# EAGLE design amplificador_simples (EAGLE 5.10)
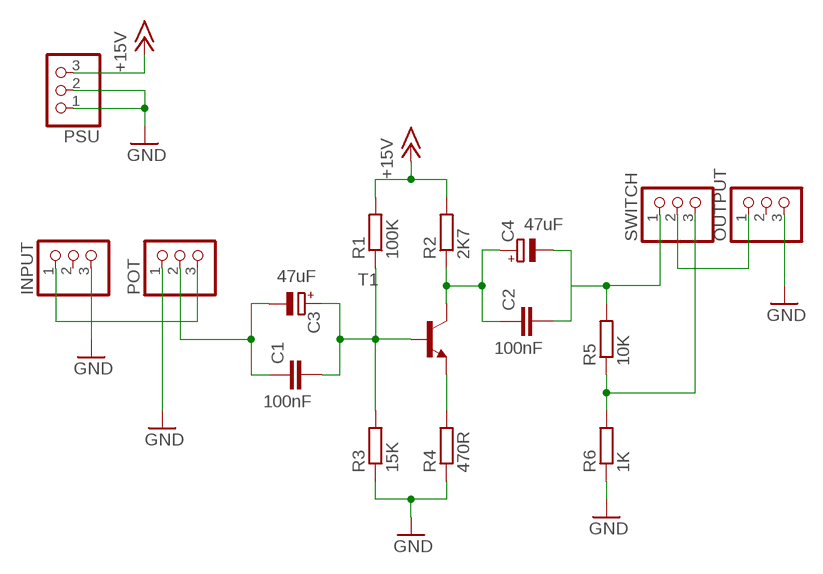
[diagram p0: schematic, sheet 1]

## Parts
C1  100nF  C-EU075-032X103  [C075-032X103]
C2  100nF  C-EU075-032X103  [C075-032X103]
C3  47uF  CPOL-EUE5-8.5  [E5-8,5]
C4  47uF  CPOL-EUE5-8.5  [E5-8,5]
INPUT  PINHD-1X3  [1X03]
OUTPUT  PINHD-1X3  [1X03]
POT  PINHD-1X3  [1X03]
PSU  PINHD-1X3  [1X03]
R1  100K  R-EU_0207/10  [0207/10]
R2  2K7  R-EU_0207/10  [0207/10]
R3  15K  R-EU_0207/10  [0207/10]
R4  470R  R-EU_0207/10  [0207/10]
R5  10K  R-EU_0207/10  [0207/10]
R6  1K  R-EU_0207/10  [0207/10]
SWITCH  PINHD-1X3  [1X03]
T1  BC548B-NPN-TO92-EBC  [TO92-EBC]

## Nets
+15V: PSU.3 R1.2 R2.2
GND: INPUT.3 OUTPUT.3 POT.1 PSU.1 PSU.2 R3.1 R4.1 R6.1
N$1: C2.1 C4.+ R2.1 T1.C
N$2: R4.2 T1.E
N$3: INPUT.1 POT.3
N$4: C1.2 C3.+ R1.1 R3.2 T1.B
N$5: R5.1 R6.2 SWITCH.3
N$6: OUTPUT.1 SWITCH.2
N$8: C2.2 C4.- R5.2 SWITCH.1
N$9: C1.1 C3.- POT.2
Unconnected: INPUT.2 OUTPUT.2

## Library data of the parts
C1 C2 = resistor:C-EU: CAPACITOR, European symbol
C3 C4 = resistor:CPOL-EU: POLARIZED CAPACITOR, European symbol
INPUT OUTPUT POT PSU SWITCH = pinhead:PINHD-1X3: PIN HEADER
R1-R6 = resistor:R-EU_: RESISTOR, European symbol
T1 = transistor:*-NPN-: NPN Transistror BF959 corrected 2008.03.06

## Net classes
0 default: width 0.635 mm, drill 0.635 mm, clearance 0.635 mm

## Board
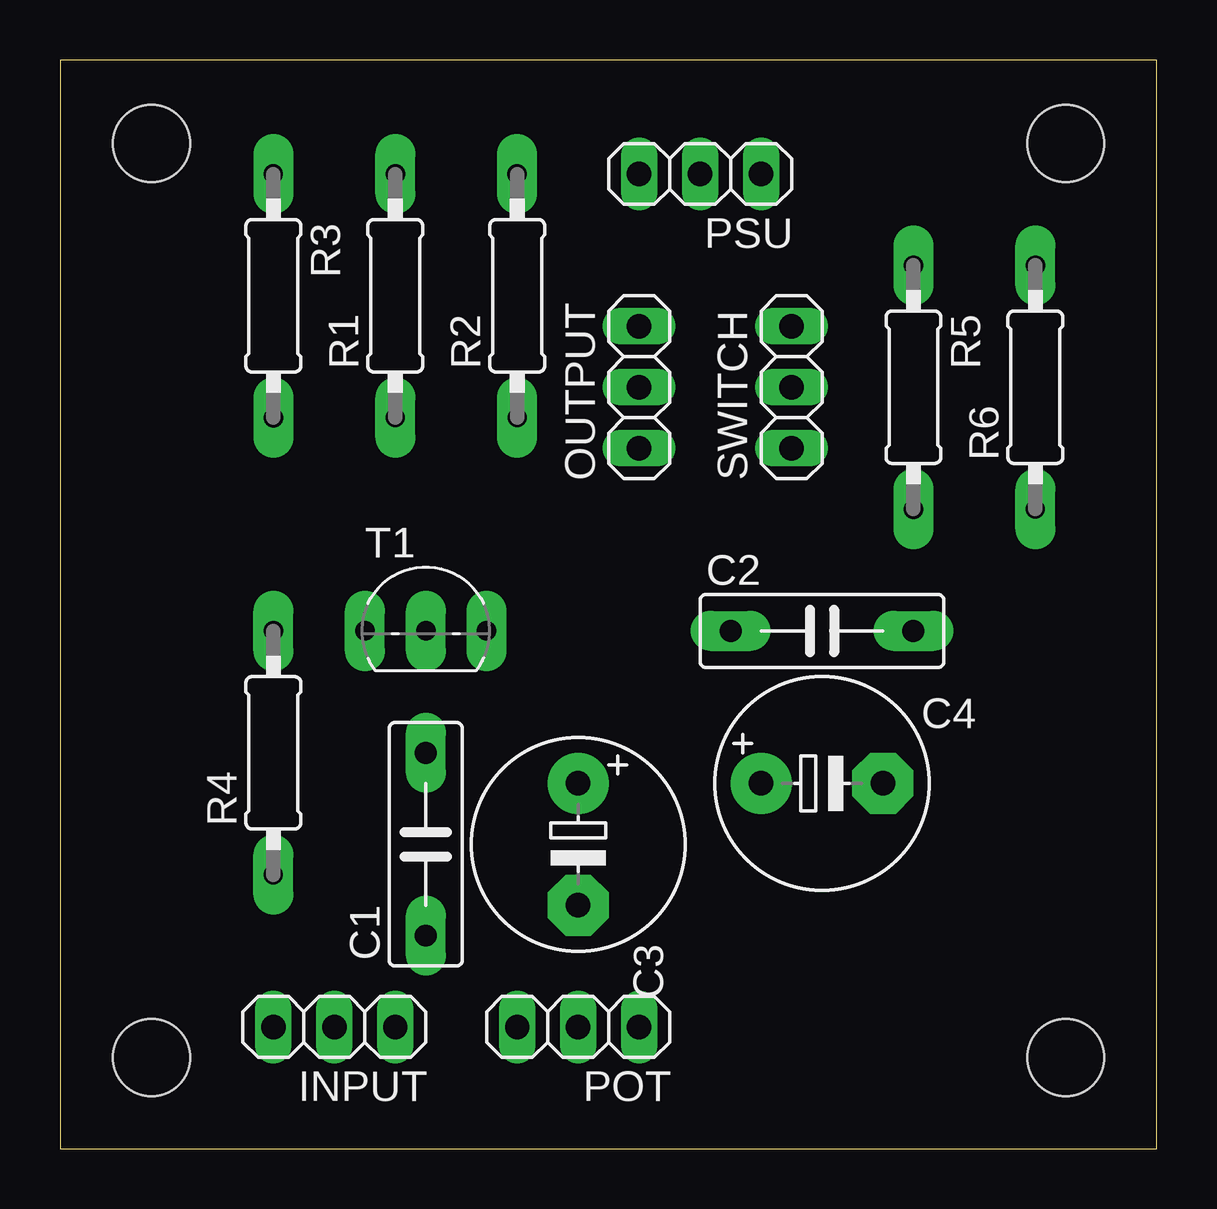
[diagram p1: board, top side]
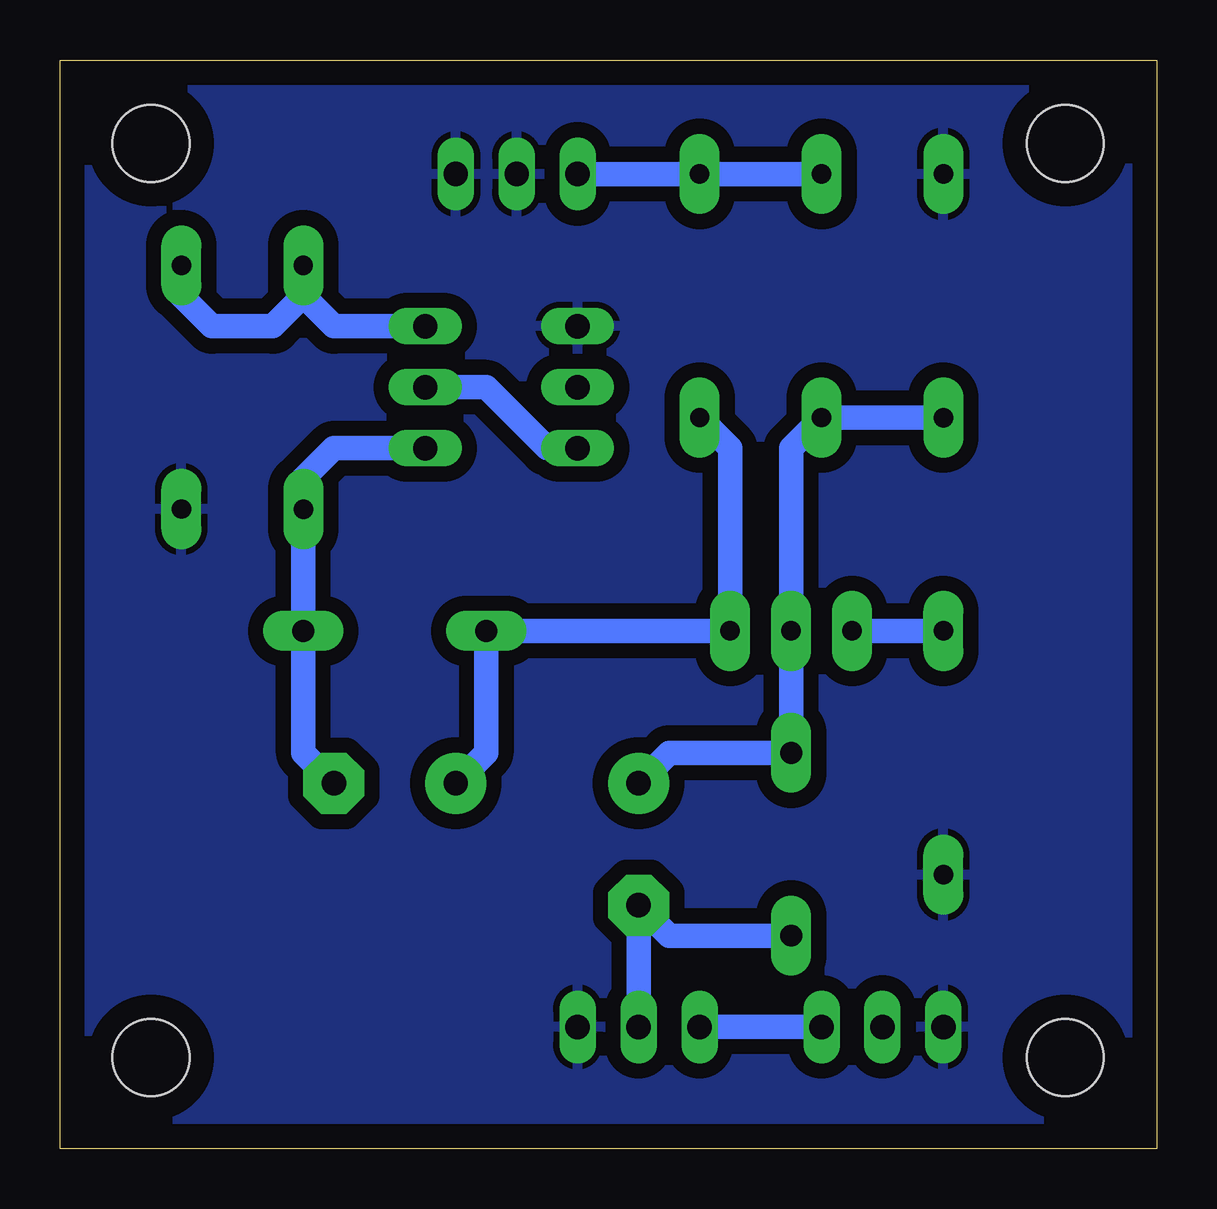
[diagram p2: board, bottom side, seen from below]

Size 45.7 x 45.39 mm. Coordinates in mm from the lower left corner, seen from the top.
Outline: 0,0 45.7,0 45.7,45.39 0,45.39 0,0
Copper layers (1*16): Top 0.035mm / dielectric 1.5mm / Bottom 0.035mm
Design rules "default": minimum track width 10mil, minimum drill 24mil, track to track 8mil, track to pad 8mil, pad to pad 8mil, via to via 8mil, smd to smd 8mil, copper to edge 40mil, drill to drill 8mil, minimum pad ring 10mil, minimum via ring 8mil, stop-mask expansion 4mil, vias tented up to drill 0mil, thermal gap 10mil
Holes 3.2 mm at 3.81,41.91 41.91,41.91 41.91,3.81 3.81,3.81

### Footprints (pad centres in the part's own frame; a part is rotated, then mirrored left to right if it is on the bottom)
C075-032X103 = drill 0.914 pad 1.676 long: 1 -3.81,0; 2 3.81,0
E5-8,5 = drill 1.016 pad 2.54 round: + -2.54,0 | drill 1.016 pad 2.54 octagon: - 2.54,0
1X03 = drill 1.016 long: 1 -2.54,0; 2 0,0; 3 2.54,0
0207/10 = drill 0.8 pad 1.676 long: 1 -5.08,0 | drill 0.813 pad 1.676 long: 2 5.08,0
TO92-EBC = drill 0.813 pad 1.676 long: B 0,-1.27; C 2.54,-1.27; E -2.54,-1.27

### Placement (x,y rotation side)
C1  15.24,12.7 90 top
C2  31.75,21.59 0 top
C3  21.59,12.7 270 top
C4  31.75,15.24 0 top
INPUT  11.43,5.08 180 top
OUTPUT  24.13,31.75 90 top
POT  21.59,5.08 180 top
PSU  26.67,40.64 180 top
R1  13.97,35.56 90 top
R2  19.05,35.56 90 top
R3  8.89,35.56 270 top
R4  8.89,16.51 90 top
R5  35.56,31.75 270 top
R6  40.64,31.75 90 top
SWITCH  30.48,31.75 90 top
T1  15.24,22.86 0 top

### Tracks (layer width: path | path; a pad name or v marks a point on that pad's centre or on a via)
+15V
  Bottom 1.016: PSU.3 R2.2 R1.2
GND
  pour Bottom: -1.27,46.99 46.99,46.99 46.99,-1.27 -1.27,-1.27
N$1
  Bottom 1.016: R2.1 17.78,29.21 T1.C C2.1 27.94,16.51 C4.+
N$2
  Bottom 1.016: R4.2 T1.E
N$3
  Bottom 1.016: INPUT.1 POT.3
N$4
  Bottom 1.016: R3.2 R1.1 15.24,29.21 T1.B C1.2 20.32,16.51 C3.+
N$5
  Bottom 1.016: SWITCH.3 34.29,34.29 35.56,35.56 | 35.56,35.56 R5.1 | 35.56,35.56 36.83,34.29 39.37,34.29 40.64,35.56 R6.2
N$6
  Bottom 1.016: OUTPUT.1 25.4,29.21 27.94,31.75 SWITCH.2
N$8
  Bottom 1.016: C4.- 35.56,16.51 C2.2 R5.2 35.56,27.94 34.29,29.21 SWITCH.1
N$9
  Bottom 1.016: C1.1 20.32,8.89 C3.- POT.2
